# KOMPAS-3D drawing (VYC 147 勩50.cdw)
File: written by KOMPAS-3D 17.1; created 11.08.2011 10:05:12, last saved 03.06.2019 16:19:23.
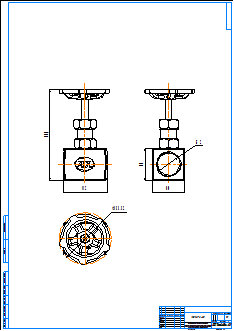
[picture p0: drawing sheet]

Sheet 1: A1, portrait

Title block, sheet 1: name: VYC 147 Ду50; material: Внимание! Данный продукт является объектом авторского права ООО «Торговый Дом АДЛ». / Запрещается изменение, копирование, распространение / (в том числе путем копирования на другие сайты и ресурсы в Интернете) / или любое иное использование информации и объектов без предварительного / согласия правообладателя (ООО «Торговый Дом АДЛ»).; scale: 1:1; sheets: 1; organisation: ООО "Торговый дом АДЛ"; sheet format: A1; stored path: \\adlc.lan\data\АДЛ_ПКД\3D-модели\Поставщики\VYC Industrial\VYC 147\KOMPAS 2D\VYC 147 Ду50.cdw

Views: Спереди 1, Проекционный вид 2, Проекционный вид 3
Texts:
  bsv
  adl
Dimensions and other numbers on the sheet: 112; 231; 80; 133,32; 1:1; 1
